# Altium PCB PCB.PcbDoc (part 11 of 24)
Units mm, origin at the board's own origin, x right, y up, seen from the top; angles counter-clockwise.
Board outline 100 x 160 mm, 10 copper layers (TOP_L1, L2, L3, L4, L5, L6, L7, L8, L9, BOTTOM_L10), stack 1.946 mm thick; 1358 components, 1149 nets, 6777 pads, 10914 vias.
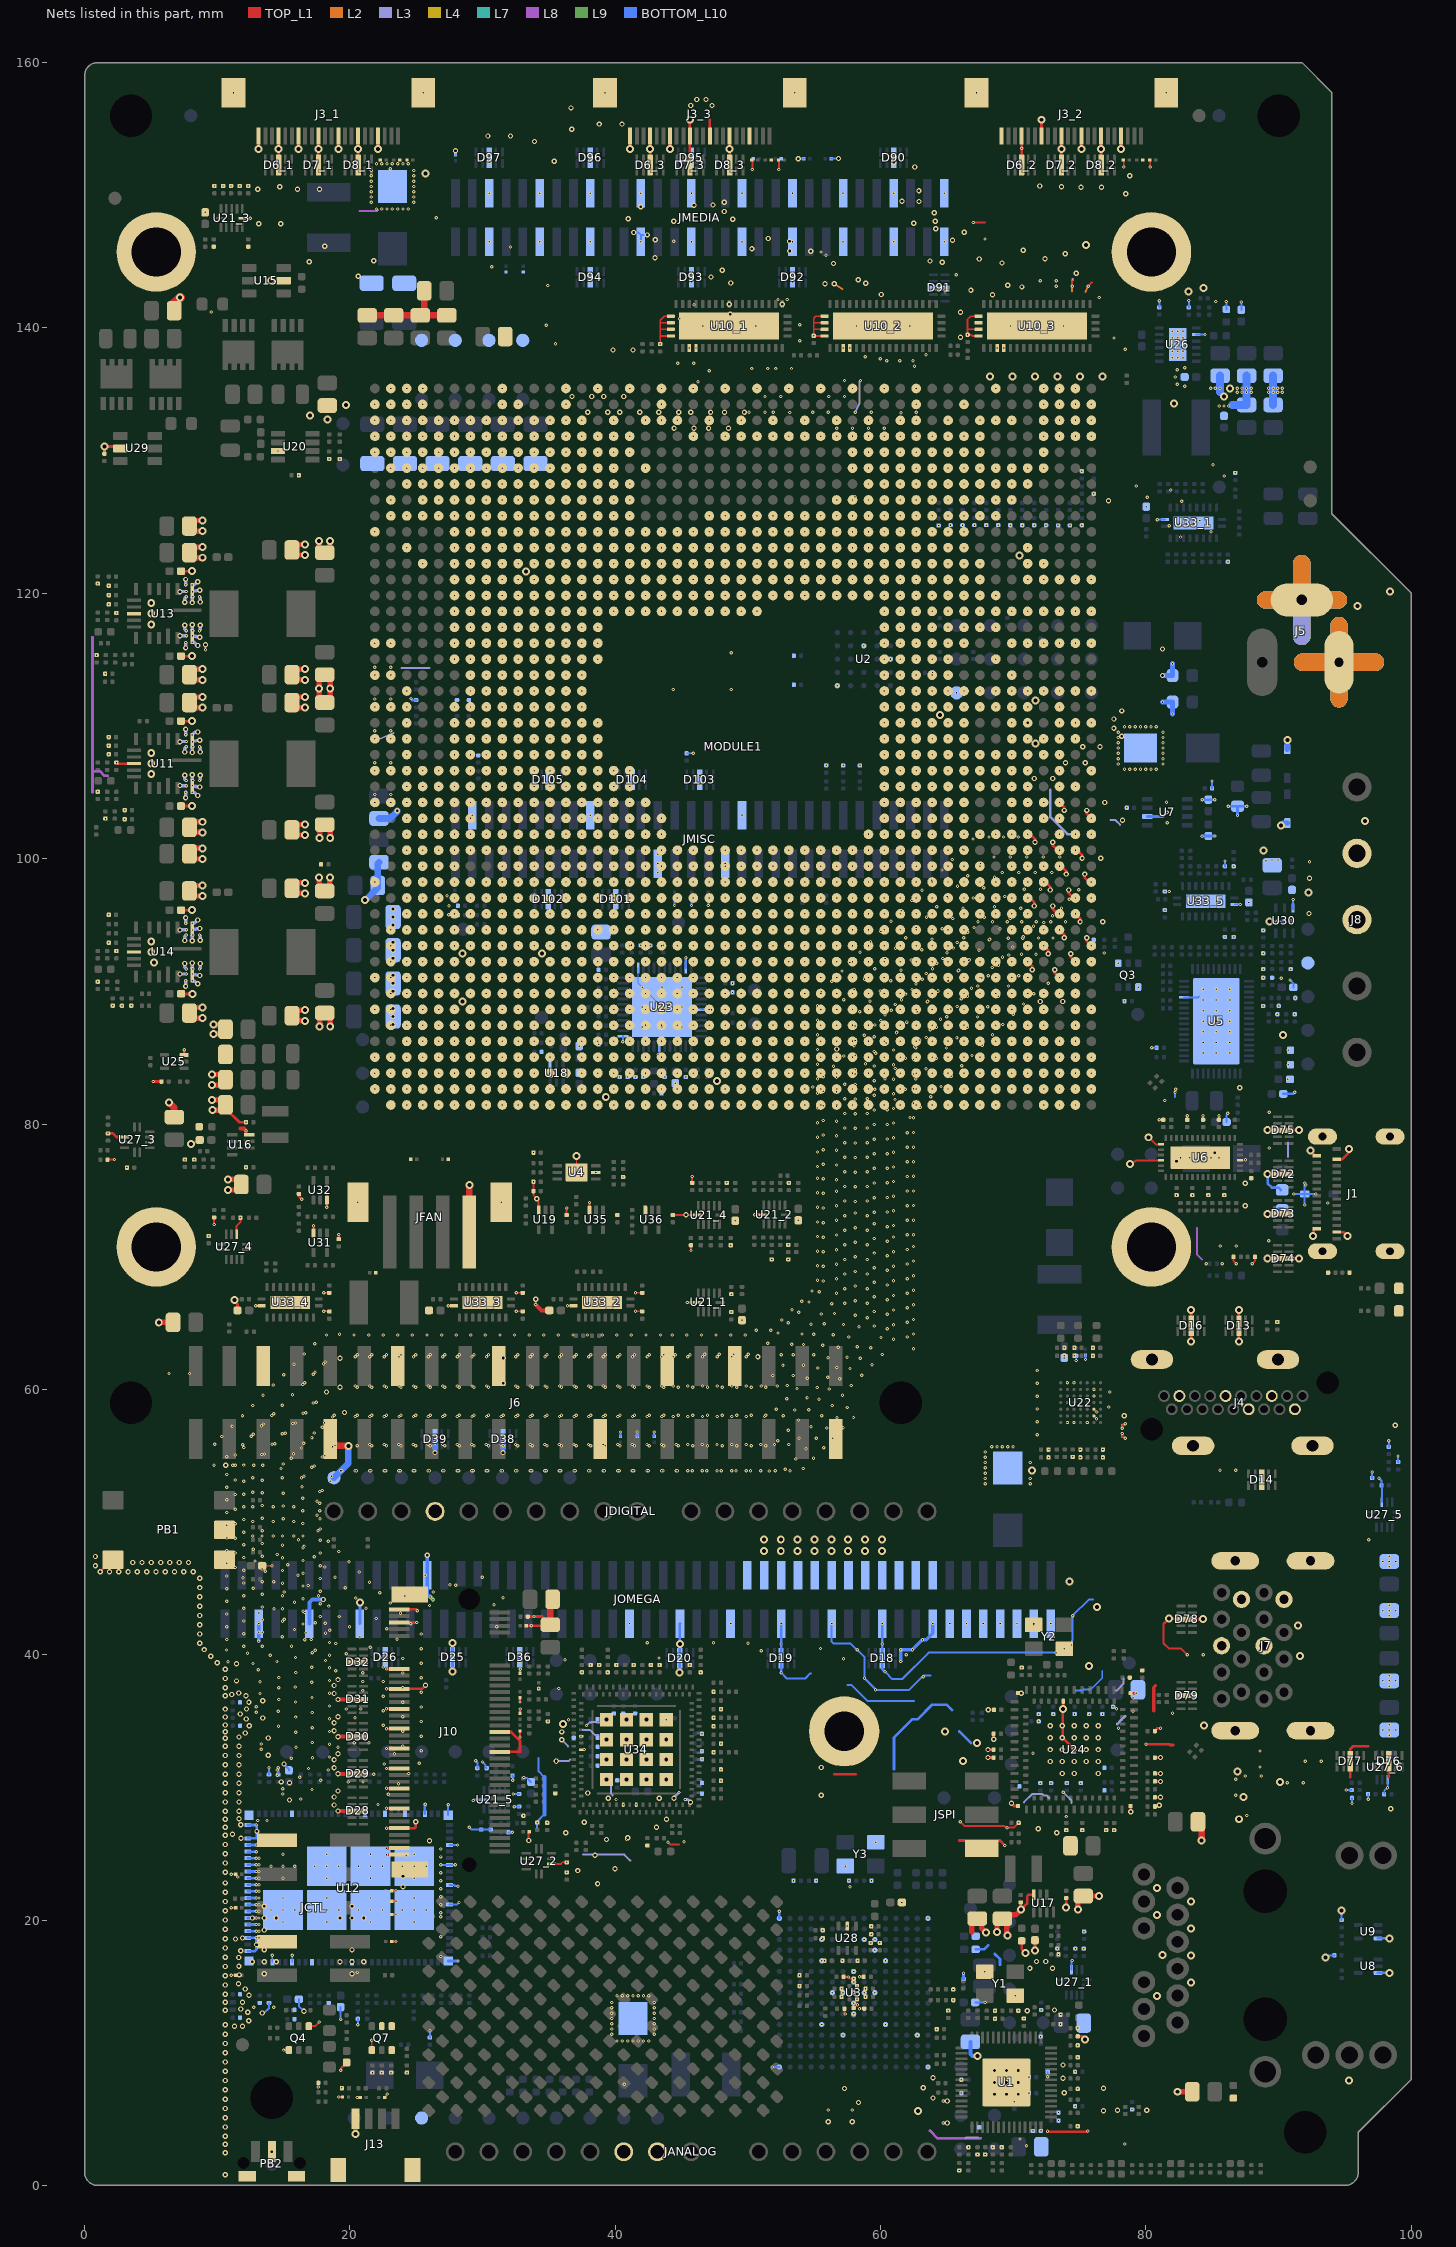
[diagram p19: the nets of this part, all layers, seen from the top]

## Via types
v1: diameter 0.25, hole 0.1, TOP_L1 to L2, tented both sides, 3439 vias
v2: diameter 0.25, hole 0.1, L2 to L3, tented both sides, 2256 vias
v3: diameter 0.25, hole 0.1, L9 to BOTTOM_L10, tented both sides, 1685 vias
v4: diameter 0.25, hole 0.1, L8 to L9, tented both sides, 1675 vias
v5: diameter 0.4, hole 0.2, L3 to L8, tented both sides, 1251 vias
v6: diameter 0.6, hole 0.3, TOP_L1 to BOTTOM_L10, tented both sides, 600 vias
v7: diameter 0.24, hole 0.1, TOP_L1 to L2, tented both sides, 8 vias

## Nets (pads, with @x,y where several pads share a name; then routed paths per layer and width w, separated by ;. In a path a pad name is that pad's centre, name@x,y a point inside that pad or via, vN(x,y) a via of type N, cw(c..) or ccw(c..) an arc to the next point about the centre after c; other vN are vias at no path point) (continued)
GND: C1.1 C2.1 C3.1 C4.1 C5.1 C6.1 C7.1 C8.1 C9.1 C10.1 C11.1 C12.1 C13.1 C14.1 C15.1 C16.1 C17.1 C18.1 C19.1 C20.1 C21.1 C22.1 C23.2 C24.2 C25.1 C26.1 C27.1 C28.1 C29.1 C30.1 C31.1 C32.1 C33.1 C34.1 C35.1 C36.1 C37.1 C38.1 C39.1 C40.1 C41.1 C42.1 C43.1 C44.2 C45.1 C46.1 C47.1 C48.1 C49.1 C54.1 C55.1 C56.1 C57.1 C58.1 C59.1 C60.1 C61.1 C62.1 C63.1 C64.2 C65.1 C66.2 C67.1 C68.1 C69_1.1 C69_2.1 C69_3.1 C70.2 C71.1 C72.1 C73.2 C74.2 C76.2 C77.2 C78.2 C79.2 C81.1 C82.1 C83.1 C84.1 C85.1 C87.2 C88.2 C89.2 C90.2 C92.2 C93.2 C94.1 C95.1 C97.2 C98.2 C99.2 C100.2 C101.1 C103.1 C104.1 C105.2 C106.1 C107.1 C108.1 C109.1 C110.1 C111.1 C114.1 C115.1 C116.2 C117.1 C118.1 C119.1 C120.1 C122.1 C123.1 C124.1 C125.1 C127.2 C128.1 C129.1 C130.1 C131.1 C132.2 C133.2 C134.1 C135.2 C136.1 C137.1 C139.2 C140.2 C141.2 C142.2 C143.2 C144.1 C145.1 C146.1 C147.1 C148.2 C149.2 C150.1 C151.1 C152.1 C153.1 C154.1 C155.1 C156.1 C157.1 C158.1 C159.1 C160.1 C161.1 C163.1 C164.1 C165.1 C166.1 C167.1 C168.1 C169.1 C170.1 C171.1 C172_1.1 C172_2.1 C172_3.1 C172_4.1 C172_5.1 C173_1.1 C173_2.1 C173_3.1 C173_4.1 C173_5.1 C174_1.1 C174_2.1 C174_3.1 C174_4.1 C174_5.1 C175_1.1 C175_2.1 C175_3.1 C175_4.1 C175_5.1 C176_1.2 C176_2.2 C176_3.2 C176_4.2 C176_5.2 C177.1 C178.1 C179_1.1 C179_2.1 C179_3.1 C179_4.1 C179_5.1 C179_6.1 C180.1 C181.1 C182.1 C183.1 C184.1 C185.1 C186.1 C187.1 C188.1 C189.1 C190.1 C191.1 C192.1 C193.1 C194.1 C195.1 C196.1 C197.1 C198.1 C199.1 C200.1 C201.1 C202.1 C203.1 C204.1 C205.1 C206.1 C207.1 C208.1 C210.1 C211.1 C212.1 C213.1 C214.1 C215.1 C216.1 C220_1.2 C220_2.2 C220_3.2 C220_4.2 C220_5.2 C221.1 C222.1 C223.1 C224.1 C225.1 C226.1 C227.1 C228.1 C229.1 C230.1 C231.1 C232.1 C233.1 C234.1 C235.1 C236.1 C237.1 C238.1 C239.1 C240.1 C241.1 C242.1 C243.1 C244.1 C245.1 C246_1.1 C246_2.1 C246_3.1 C246_4.1 C246_5.1 C246_6.1 C248.1 C249.1 C250.1 C251.1 C252.1 C255.1 C257.1 C258.1 C259.2 C260.1 C261.2 C262.1 C263.1 C264.2 C265.1 C266.1 C267.1 C268.1 C269.1 C270.1 C271.1 C272.1 C273.1 C274.1 C275.1 C276.1 C277.1 C278.1 C279.1 C281.1 C282.1 C285.1 C286.2 C287.2 C288.2 C291.1 C292.1 C294.1 C295.1 C296.2 C300.1 C302.1 C303.2 C304.1 C305.1 C306.1 C308.1 C311.1 C312.1 C313.1 C314.1 C315.1 C316.1 C317.1 C318.1 C319.2 C320.2 C321.2 C328.1 C329.1 C330.1 C331.1 C332.2 C333.2 C334.2 C335.2 C336.2 C337.2 C338.1 C339.2 C340.2 C341.2 C342.2 C343.2 C344.2 C345.1 C346.1 C347.1 C348.1 C351.2 C352.2 C353.2 C354.2 C355.1 C356.2 C357.2 C359.1 C360.1 C361.2 D1.1 D2.1 D5.1 D6_1.3 D6_1.8 D6_2.3 D6_2.8 D6_3.3 D6_3.8 D7_1.3 D7_1.8 D7_2.3 D7_2.8 D7_3.3 D7_3.8 D8_1.3 D8_1.8 D8_2.3 D8_2.8 D8_3.3 D8_3.8 D10_1.1 D10_2.1 D10_3.1 D11_1.1 D11_2.1 D11_3.1 D12.1 D13.3 D13.8 D14.3 D14.8 D15_1.1 D15_2.1 D15_3.1 D16.3 D16.8 D17.1 D18.3 D18.8 D19.3 D19.8 D20.3 D20.8 D21.1 D22.1 D23.1 D24.1 D25.3 D25.8 D26.3 D26.8 D27.1 D28.3 D28.8 D29.3 D29.8 D30.3 D30.8 D31.3 D31.8 D32.3 D32.8 D33.1 D34.1 D35.1 D36.3 D36.8 D37.1 D38.3 D38.8 D39.3 D39.8 D40.1 D41.1 D42.1 D43.1 D61.1 D62.1 D63.1 D64.1 D65.1 D66.1 D67.1 D69.1 D70.1 D71.1 D72.3 D72.8 D73.3 D73.8 D74.3 D74.8 D75.3 D75.8 D76.3 D76.8 D77.3 D77.8 D78.3 D78.8 D79.3 D79.8 D80.1 D81.1 D82.1 D83.1 D84.1 D85.1 D86.1 D87.1 D88.1 D89.1 D90.3 D90.8 D91.3 D91.8 D92.3 D92.8 D93.3 D93.8 D94.3 D94.8 D95.3 D95.8 D96.3 D96.8 D97.3 D97.8 D98.1 D99.1 D100.1 D101.3 D101.8 D102.3 D102.8 D103.3 D103.8 D104.3 D104.8 D105.3 D105.8 D106.1 DL2.C DL3.C H1.1 H2.1 H3.1 H4.1 H5.1 J1.A1 J1.A12 J1.B1 J1.B12 J1.SHIELD1 J1.SHIELD2 J1.SHIELD3 J1.SHIELD4 J3_1.1 J3_1.4 J3_1.7 J3_1.10 J3_1.13 J3_1.16 J3_1.19 J3_1.FIX J3_2.1 J3_2.4 J3_2.7 J3_2.10 J3_2.13 J3_2.16 J3_2.19 J3_2.FIX J3_3.1 J3_3.4 J3_3.7 J3_3.10 J3_3.13 J3_3.16 J3_3.19 J3_3.FIX J4.2 J4.5 J4.8 J4.11 J4.17 J4.SH1 J4.SH2 J4.SH3 J4.SH4 J5.2 J5.3 J6.6 J6.9 J6.14 J6.20 J6.25 J6.30 J6.34 J6.39 J7.4 J7.7 J7.13 J7.16 J7.19 J7.20 J7.21 J7.22 J8.2 J8.3 J10.1 J10.3 J10.9 J10.15 J10.21 J10.27 J10.32 J10.33 J10.38 J10.39 J10.45 J10.51 J10.57 J10.71 J10.75 J10.FIXING J13.1 J13.FIX JANALOG.6 JANALOG.7 JCTL.1 JCTL.7 JDIGITAL.15 JFAN.4 JFAN.FIX JMEDIA.1 JMEDIA.2 JMEDIA.7 JMEDIA.8 JMEDIA.13 JMEDIA.14 JMEDIA.19 JMEDIA.20 JMEDIA.25 JMEDIA.26 JMEDIA.31 JMEDIA.32 JMEDIA.37 JMEDIA.38 JMEDIA.43 JMEDIA.44 JMEDIA.49 JMEDIA.50 JMEDIA.55 JMEDIA.56 JMISC.26 JMISC.27 JMISC.35 JMISC.44 JMISC.58 JOMEGA.2 JOMEGA.4 JOMEGA.6 JOMEGA.8 JOMEGA.10 JOMEGA.12 JOMEGA.14 JOMEGA.15 JOMEGA.16 JOMEGA.17 JOMEGA.19 JOMEGA.21 JOMEGA.22 JOMEGA.23 JOMEGA.25 JOMEGA.27 JOMEGA.28 JOMEGA.29 JOMEGA.31 JOMEGA.33 JOMEGA.34 JOMEGA.35 JOMEGA.37 JOMEGA.40 JOMEGA.46 JOMEGA.52 JOMEGA.75 JOMEGA.84 JOMEGA.90 JOMEGA.96 JSPI.6 MODULE1.A2 MODULE1.A3 MODULE1.A4 MODULE1.A7 MODULE1.A9 MODULE1.A15 MODULE1.A20 MODULE1.A22 MODULE1.A24 MODULE1.A26 MODULE1.A28 MODULE1.A30 MODULE1.A37 MODULE1.A42 MODULE1.A43 MODULE1.A44 MODULE1.A45 MODULE1.AA1 MODULE1.AA2 MODULE1.AA3 MODULE1.AA4 MODULE1.AA5 MODULE1.AA6 MODULE1.AA7 MODULE1.AA8 MODULE1.AA9 MODULE1.AA10 MODULE1.AA11 MODULE1.AA12 MODULE1.AA13 MODULE1.AA14 MODULE1.AA15 MODULE1.AA16 MODULE1.AA17 MODULE1.AA32 MODULE1.AA33 MODULE1.AA34 MODULE1.AA35 MODULE1.AA36 MODULE1.AA37 MODULE1.AA43 MODULE1.AA46 MODULE1.AB1 MODULE1.AB2 MODULE1.AB3 MODULE1.AB4 MODULE1.AB5 MODULE1.AB6 MODULE1.AB7 MODULE1.AB8 MODULE1.AB9 MODULE1.AB10 MODULE1.AB11 MODULE1.AB12 MODULE1.AB13 MODULE1.AB14 MODULE1.AB15 MODULE1.AB16 MODULE1.AB17 MODULE1.AB32 MODULE1.AB33 MODULE1.AB34 MODULE1.AB35 MODULE1.AB36 MODULE1.AB37 MODULE1.AB38 MODULE1.AB44 MODULE1.AC1 MODULE1.AC2 MODULE1.AC3 MODULE1.AC4 MODULE1.AC5 MODULE1.AC6 MODULE1.AC7 MODULE1.AC8 MODULE1.AC9 MODULE1.AC10 MODULE1.AC11 MODULE1.AC12 MODULE1.AC13 MODULE1.AC14 MODULE1.AC15 MODULE1.AC16 MODULE1.AC17 MODULE1.AC32 MODULE1.AC33 MODULE1.AC34 MODULE1.AC35 MODULE1.AC36 MODULE1.AC37 MODULE1.AC38 MODULE1.AC43 MODULE1.AC46 MODULE1.AD1 MODULE1.AD2 MODULE1.AD3 MODULE1.AD4 MODULE1.AD5 MODULE1.AD6 MODULE1.AD7 MODULE1.AD8 MODULE1.AD9 MODULE1.AD10 MODULE1.AD11 MODULE1.AD12 MODULE1.AD13 MODULE1.AD14 MODULE1.AD15 MODULE1.AD16 MODULE1.AD17 MODULE1.AD32 MODULE1.AD33 MODULE1.AD34 MODULE1.AD35 MODULE1.AD36 MODULE1.AD37 MODULE1.AD38 MODULE1.AD43 MODULE1.AD44 MODULE1.AE1 MODULE1.AE2 MODULE1.AE3 MODULE1.AE4 MODULE1.AE5 MODULE1.AE6 MODULE1.AE7 MODULE1.AE8 MODULE1.AE9 MODULE1.AE10 MODULE1.AE11 MODULE1.AE12 MODULE1.AE13 MODULE1.AE14 MODULE1.AE15 MODULE1.AE16 MODULE1.AE17 MODULE1.AE32 MODULE1.AE33 MODULE1.AE34 MODULE1.AE35 MODULE1.AE36 MODULE1.AE37 MODULE1.AE38 MODULE1.AE43 MODULE1.AE46 MODULE1.AF1 MODULE1.AF2 MODULE1.AF3 MODULE1.AF4 MODULE1.AF5 MODULE1.AF6 MODULE1.AF7 MODULE1.AF8 MODULE1.AF9 MODULE1.AF10 MODULE1.AF11 MODULE1.AF12 MODULE1.AF13 MODULE1.AF14 MODULE1.AF15 MODULE1.AF16 MODULE1.AF17 MODULE1.AF33 MODULE1.AF34 MODULE1.AF35 MODULE1.AF36 MODULE1.AF37 MODULE1.AF38 MODULE1.AF43 MODULE1.AF44 MODULE1.AG1 MODULE1.AG2 MODULE1.AG3 MODULE1.AG4 MODULE1.AG5 MODULE1.AG6 MODULE1.AG7 MODULE1.AG8 MODULE1.AG9 MODULE1.AG10 MODULE1.AG11 MODULE1.AG12 MODULE1.AG13 MODULE1.AG14 MODULE1.AG15 MODULE1.AG16 MODULE1.AG17 MODULE1.AG33 MODULE1.AG34 MODULE1.AG35 MODULE1.AG36 MODULE1.AG37 MODULE1.AG38 MODULE1.AG43 MODULE1.AG46 MODULE1.AH1 MODULE1.AH2 MODULE1.AH3 MODULE1.AH4 MODULE1.AH5 MODULE1.AH6 MODULE1.AH7 MODULE1.AH8 MODULE1.AH9 MODULE1.AH10 MODULE1.AH11 MODULE1.AH12 MODULE1.AH13 MODULE1.AH14 MODULE1.AH15 MODULE1.AH16 MODULE1.AH17 MODULE1.AH33 MODULE1.AH34 MODULE1.AH35 MODULE1.AH36 MODULE1.AH37 MODULE1.AH38 MODULE1.AH43 MODULE1.AH44 MODULE1.AJ1 MODULE1.AJ2 MODULE1.AJ3 MODULE1.AJ4 MODULE1.AJ5 MODULE1.AJ6 MODULE1.AJ7 MODULE1.AJ8 MODULE1.AJ9 MODULE1.AJ10 MODULE1.AJ11 MODULE1.AJ12 MODULE1.AJ13 MODULE1.AJ14 MODULE1.AJ15 MODULE1.AJ16 MODULE1.AJ17 MODULE1.AJ33 MODULE1.AJ34 MODULE1.AJ35 MODULE1.AJ36 MODULE1.AJ37 MODULE1.AJ38 MODULE1.AJ43 MODULE1.AJ46 MODULE1.AK1 MODULE1.AK2 MODULE1.AK3 MODULE1.AK4 MODULE1.AK5 MODULE1.AK6 MODULE1.AK7 MODULE1.AK8 MODULE1.AK9 MODULE1.AK10 MODULE1.AK11 MODULE1.AK12 MODULE1.AK13 MODULE1.AK14 MODULE1.AK15 MODULE1.AK16 MODULE1.AK17 MODULE1.AK33 MODULE1.AK34 MODULE1.AK35 MODULE1.AK36 MODULE1.AK37 MODULE1.AK38 MODULE1.AK39 MODULE1.AK43 MODULE1.AK44 MODULE1.AL1 MODULE1.AL2 MODULE1.AL3 MODULE1.AL4 MODULE1.AL5 MODULE1.AL6 MODULE1.AL7 MODULE1.AL8 MODULE1.AL9 MODULE1.AL10 MODULE1.AL11 MODULE1.AL12 MODULE1.AL13 MODULE1.AL14 MODULE1.AL15 MODULE1.AL16 MODULE1.AL17 MODULE1.AL33 MODULE1.AL34 MODULE1.AL35 MODULE1.AL36 MODULE1.AL37 MODULE1.AL38 MODULE1.AL39 MODULE1.AL41 MODULE1.AL42 MODULE1.AL43 MODULE1.AL46 MODULE1.AM1 MODULE1.AM2 MODULE1.AM3 MODULE1.AM4 MODULE1.AM5 MODULE1.AM6 MODULE1.AM7 MODULE1.AM8 MODULE1.AM9 MODULE1.AM10 MODULE1.AM11 MODULE1.AM12 MODULE1.AM13 MODULE1.AM14 MODULE1.AM15 MODULE1.AM16 MODULE1.AM17 MODULE1.AM18 MODULE1.AM33 MODULE1.AM34 MODULE1.AM35 MODULE1.AM36 MODULE1.AM37 MODULE1.AM38 MODULE1.AM39 MODULE1.AM40 MODULE1.AM41 MODULE1.AM42 MODULE1.AM43 MODULE1.AM44 MODULE1.AN1 MODULE1.AN2 MODULE1.AN3 MODULE1.AN4 MODULE1.AN5 MODULE1.AN6 MODULE1.AN7 MODULE1.AN8 MODULE1.AN9 MODULE1.AN10 MODULE1.AN11 MODULE1.AN12 MODULE1.AN13 MODULE1.AN14 MODULE1.AN15 MODULE1.AN16 MODULE1.AN17 MODULE1.AN18 MODULE1.AN19 MODULE1.AN20 MODULE1.AN21 MODULE1.AN22 MODULE1.AN23 MODULE1.AN24 MODULE1.AN25 MODULE1.AN26 MODULE1.AN27 MODULE1.AN28 MODULE1.AN29 MODULE1.AN30 MODULE1.AN31 MODULE1.AN32 MODULE1.AN33 MODULE1.AN34 MODULE1.AN35 MODULE1.AN36 MODULE1.AN37 MODULE1.AN38 MODULE1.AN39 MODULE1.AN40 MODULE1.AN41 MODULE1.AN42 MODULE1.AN43 MODULE1.AN46 MODULE1.AP1 MODULE1.AP2 MODULE1.AP3 MODULE1.AP4 MODULE1.AP5 MODULE1.AP6 MODULE1.AP7 MODULE1.AP8 MODULE1.AP9 MODULE1.AP10 MODULE1.AP11 MODULE1.AP12 MODULE1.AP13 MODULE1.AP14 MODULE1.AP15 MODULE1.AP16 MODULE1.AP17 MODULE1.AP18 MODULE1.AP19 MODULE1.AP20 MODULE1.AP21 MODULE1.AP22 MODULE1.AP23 MODULE1.AP24 MODULE1.AP25 MODULE1.AP26 MODULE1.AP27 MODULE1.AP28 MODULE1.AP29 MODULE1.AP30 MODULE1.AP31 MODULE1.AP32 MODULE1.AP33 MODULE1.AP34 MODULE1.AP35 MODULE1.AP36 MODULE1.AP37 MODULE1.AP38 MODULE1.AP39 MODULE1.AP40 MODULE1.AP41 MODULE1.AP42 MODULE1.AP43 MODULE1.AP44 MODULE1.AR1 MODULE1.AR2 MODULE1.AR3 MODULE1.AR4 MODULE1.AR5 MODULE1.AR6 MODULE1.AR7 MODULE1.AR8 MODULE1.AR9 MODULE1.AR10 MODULE1.AR11 MODULE1.AR12 MODULE1.AR13 MODULE1.AR14 MODULE1.AR15 MODULE1.AR16 MODULE1.AR17 MODULE1.AR18 MODULE1.AR19 MODULE1.AR20 MODULE1.AR21 MODULE1.AR22 MODULE1.AR23 MODULE1.AR24 MODULE1.AR25 MODULE1.AR26 MODULE1.AR27 MODULE1.AR28 MODULE1.AR29 MODULE1.AR30 MODULE1.AR31 MODULE1.AR32 MODULE1.AR33 MODULE1.AR34 MODULE1.AR35 MODULE1.AR36 MODULE1.AR37 MODULE1.AR38 MODULE1.AR39 MODULE1.AR40 MODULE1.AR41 MODULE1.AR42 MODULE1.AR43 MODULE1.AR44 MODULE1.AR45 MODULE1.AR46 MODULE1.AT1 MODULE1.AT2 MODULE1.AT3 MODULE1.AT4 MODULE1.AT5 MODULE1.AT6 MODULE1.AT7 MODULE1.AT8 MODULE1.AT9 MODULE1.AT10 MODULE1.AT11 MODULE1.AT12 MODULE1.AT13 MODULE1.AT14 MODULE1.AT15 MODULE1.AT16 MODULE1.AT17 MODULE1.AT18 MODULE1.AT19 MODULE1.AT20 MODULE1.AT21 MODULE1.AT22 MODULE1.AT23 MODULE1.AT24 MODULE1.AT25 MODULE1.AT26 MODULE1.AT27 MODULE1.AT28 MODULE1.AT29 MODULE1.AT30 MODULE1.AT31 MODULE1.AT32 MODULE1.AT33 MODULE1.AT34 MODULE1.AT35 MODULE1.AT36 MODULE1.AT37 MODULE1.AT38 MODULE1.AT39 MODULE1.AT40 MODULE1.AT41 MODULE1.AT42 MODULE1.AT43 MODULE1.AU1 MODULE1.AU2 MODULE1.AU3 MODULE1.AU4 MODULE1.AU5 MODULE1.AU6 MODULE1.AU7 MODULE1.AU8 MODULE1.AU9 MODULE1.AU10 MODULE1.AU11 MODULE1.AU12 MODULE1.AU13 MODULE1.AU14 MODULE1.AU15 MODULE1.AU16 MODULE1.AU17 MODULE1.AU18 MODULE1.AU19 MODULE1.AU20 MODULE1.AU21 MODULE1.AU22 MODULE1.AU23 MODULE1.AU24 MODULE1.AU25 MODULE1.AU26 MODULE1.AU27 MODULE1.AU28 MODULE1.AU29 MODULE1.AU30 MODULE1.AU31 MODULE1.AU32 MODULE1.AU33 MODULE1.AU34 MODULE1.AU35 MODULE1.AU36 MODULE1.AU37 MODULE1.AU38 MODULE1.AU39 MODULE1.AU40 MODULE1.AU41 MODULE1.AU42 MODULE1.AU43 MODULE1.AU44 MODULE1.AV1 MODULE1.AV2 MODULE1.AV3 MODULE1.AV4 MODULE1.AV5 MODULE1.AV6 MODULE1.AV7 MODULE1.AV8 MODULE1.AV9 MODULE1.AV10 MODULE1.AV11 MODULE1.AV12 MODULE1.AV13 MODULE1.AV14 MODULE1.AV15 MODULE1.AV16 MODULE1.AV17 MODULE1.AV18 MODULE1.AV19 MODULE1.AV20 MODULE1.AV21 MODULE1.AV22 MODULE1.AV23 MODULE1.AV24 MODULE1.AV25 MODULE1.AV26 MODULE1.AV27 MODULE1.AV30 MODULE1.AV31 MODULE1.AV32 MODULE1.AV33 MODULE1.AV34 MODULE1.AV35 MODULE1.AV36 MODULE1.AV37 MODULE1.AV38 MODULE1.AV39 MODULE1.AV40 MODULE1.AV41 MODULE1.AV42 MODULE1.AV43 MODULE1.AV45 MODULE1.AW1 MODULE1.AW2 MODULE1.AW3 MODULE1.AW4 MODULE1.AW5 MODULE1.AW6 MODULE1.AW7 MODULE1.AW8 MODULE1.AW9 MODULE1.AW10 MODULE1.AW13 MODULE1.AW14 MODULE1.AW15 MODULE1.AW16 MODULE1.AW18 MODULE1.AW21 MODULE1.AW22 MODULE1.AW23 MODULE1.AW26 MODULE1.AW27 MODULE1.AW31 MODULE1.AW32 MODULE1.AW33 MODULE1.AW34 MODULE1.AW35 MODULE1.AW38 MODULE1.AW39 MODULE1.AW40 MODULE1.AW41 MODULE1.AW42 MODULE1.AW43 MODULE1.AW44 MODULE1.AY1 MODULE1.AY2 MODULE1.AY3 MODULE1.AY4 MODULE1.AY5 MODULE1.AY6 MODULE1.AY7 MODULE1.AY8 MODULE1.AY9 MODULE1.AY10 MODULE1.AY13 MODULE1.AY14 MODULE1.AY15 MODULE1.AY18 MODULE1.AY21 MODULE1.AY22 MODULE1.AY23 MODULE1.AY26 MODULE1.AY27 MODULE1.AY29 MODULE1.AY31 MODULE1.AY32 MODULE1.AY33 MODULE1.AY38 MODULE1.AY39 MODULE1.AY40 MODULE1.AY41 MODULE1.AY44 MODULE1.AY46 MODULE1.B1 MODULE1.B2 MODULE1.B3 MODULE1.B4 MODULE1.B6 MODULE1.B7 MODULE1.B8 MODULE1.B9 MODULE1.B10 MODULE1.B11 MODULE1.B12 MODULE1.B20 MODULE1.B22 MODULE1.B24 MODULE1.B26 MODULE1.B28 MODULE1.B30 MODULE1.B38 MODULE1.B39 MODULE1.B41 MODULE1.B42 MODULE1.B43 MODULE1.B44 MODULE1.B45 MODULE1.B46 MODULE1.BA2 MODULE1.BA3 MODULE1.BA4 MODULE1.BA5 MODULE1.BA6 MODULE1.BA7 MODULE1.BA8 MODULE1.BA9 MODULE1.BA10 MODULE1.BA12 MODULE1.BA13 MODULE1.BA14 MODULE1.BA15 MODULE1.BA16 MODULE1.BA17 MODULE1.BA18 MODULE1.BA19 MODULE1.BA20 MODULE1.BA21 MODULE1.BA22 MODULE1.BA23 MODULE1.BA24 MODULE1.BA25 MODULE1.BA26 MODULE1.BA27 MODULE1.BA28 MODULE1.BA30 MODULE1.BA32 MODULE1.BA39 MODULE1.BA40 MODULE1.BA41 MODULE1.BA44 MODULE1.BB2 MODULE1.BB3 MODULE1.BB4 MODULE1.BB5 MODULE1.BB6 MODULE1.BB7 MODULE1.BB8 MODULE1.BB9 MODULE1.BB10 MODULE1.BB11 MODULE1.BB12 MODULE1.BB13 MODULE1.BB14 MODULE1.BB15 MODULE1.BB16 MODULE1.BB17 MODULE1.BB18 MODULE1.BB19 MODULE1.BB20 MODULE1.BB21 MODULE1.BB22 MODULE1.BB23 MODULE1.BB24 MODULE1.BB25 MODULE1.BB26 MODULE1.BB27 MODULE1.BB30 MODULE1.BB32 MODULE1.BB34 MODULE1.BB35 MODULE1.BB36 MODULE1.BB40 MODULE1.BB41 MODULE1.BC1 MODULE1.BC2 MODULE1.BC3 MODULE1.BC4 MODULE1.BC5 MODULE1.BC6 MODULE1.BC7 MODULE1.BC8 MODULE1.BC11 MODULE1.BC12 MODULE1.BC15 MODULE1.BC16 MODULE1.BC19 MODULE1.BC20 MODULE1.BC23 MODULE1.BC24 MODULE1.BC27 MODULE1.BC30 MODULE1.BC32 MODULE1.BC34 MODULE1.BC35 MODULE1.BC41 MODULE1.BC42 MODULE1.BC43 MODULE1.BC44 MODULE1.BC45 MODULE1.BC46 MODULE1.BD1 MODULE1.BD2 MODULE1.BD3 MODULE1.BD4 MODULE1.BD5 MODULE1.BD8 MODULE1.BD9 MODULE1.BD12 MODULE1.BD13 MODULE1.BD16 MODULE1.BD17 MODULE1.BD18 MODULE1.BD19 MODULE1.BD20 MODULE1.BD21 MODULE1.BD22 MODULE1.BD23 MODULE1.BD24 MODULE1.BD25 MODULE1.BD26 MODULE1.BD27 MODULE1.BD30 MODULE1.BD32 MODULE1.BD34 MODULE1.BD43 MODULE1.BD44 MODULE1.BD45 MODULE1.BD46 MODULE1.BE1 MODULE1.BE2 MODULE1.BE3 MODULE1.BE4 MODULE1.BE5 MODULE1.BE6 MODULE1.BE7 MODULE1.BE8 MODULE1.BE9 MODULE1.BE10 MODULE1.BE13 MODULE1.BE14 MODULE1.BE17 MODULE1.BE18 MODULE1.BE21 MODULE1.BE24 MODULE1.BE25 MODULE1.BE27 MODULE1.BE30 MODULE1.BE32 MODULE1.BE34 MODULE1.BE43 MODULE1.BE44 MODULE1.BE45 MODULE1.BE46 MODULE1.BF2 MODULE1.BF3 MODULE1.BF4 MODULE1.BF7 MODULE1.BF10 MODULE1.BF11 MODULE1.BF14 MODULE1.BF15 MODULE1.BF18 MODULE1.BF19 MODULE1.BF22 MODULE1.BF25 MODULE1.BF27 MODULE1.BF30 MODULE1.BF32 MODULE1.BF34 MODULE1.BF43 MODULE1.BF44 MODULE1.BF45 MODULE1.C1 MODULE1.C2 MODULE1.C3 MODULE1.C4 MODULE1.C5 MODULE1.C6 MODULE1.C7 MODULE1.C8 MODULE1.C9 MODULE1.C10 MODULE1.C11 MODULE1.C12 MODULE1.C13 MODULE1.C14 MODULE1.C15 MODULE1.C16 MODULE1.C17 MODULE1.C18 MODULE1.C19 MODULE1.C20 MODULE1.C21 MODULE1.C22 MODULE1.C23 MODULE1.C24 MODULE1.C25 MODULE1.C26 MODULE1.C27 MODULE1.C36 MODULE1.C38 MODULE1.C40 MODULE1.C41 MODULE1.C42 MODULE1.C43 MODULE1.C44 MODULE1.C45 MODULE1.C46 MODULE1.D1 MODULE1.D2 MODULE1.D3 MODULE1.D4 MODULE1.D5 MODULE1.D6 MODULE1.D7 MODULE1.D8 MODULE1.D9 MODULE1.D10 MODULE1.D11 MODULE1.D12 MODULE1.D13 MODULE1.D14 MODULE1.D15 MODULE1.D16 MODULE1.D17 MODULE1.D18 MODULE1.D19 MODULE1.D20 MODULE1.D21 MODULE1.D22 MODULE1.D35 MODULE1.D38 MODULE1.D39 MODULE1.D40 MODULE1.D41 MODULE1.D42 MODULE1.D43 MODULE1.D44 MODULE1.D45 MODULE1.D46 MODULE1.E1 MODULE1.E2 MODULE1.E3 MODULE1.E4 MODULE1.E5 MODULE1.E6 MODULE1.E7 MODULE1.E8 MODULE1.E9 MODULE1.E10 MODULE1.E11 MODULE1.E12 MODULE1.E13 MODULE1.E14 MODULE1.E15 MODULE1.E16 MODULE1.E17 MODULE1.E18 MODULE1.E19 MODULE1.E20 MODULE1.E21 MODULE1.E22 MODULE1.E38 MODULE1.E39 MODULE1.E40 MODULE1.E41 MODULE1.E42 MODULE1.E43 MODULE1.E44 MODULE1.F1 MODULE1.F2 MODULE1.F3 MODULE1.F4 MODULE1.F5 MODULE1.F6 MODULE1.F7 MODULE1.F8 MODULE1.F9 MODULE1.F10 MODULE1.F11 MODULE1.F12 MODULE1.F13 MODULE1.F14 MODULE1.F15 MODULE1.F16 MODULE1.F17 MODULE1.F18 MODULE1.F19 MODULE1.F20 MODULE1.F21 MODULE1.F22 MODULE1.F23 MODULE1.F24 MODULE1.F25 MODULE1.F26 MODULE1.F29 MODULE1.F30 MODULE1.F31 MODULE1.F32 MODULE1.F33 MODULE1.F34 MODULE1.F35 MODULE1.F36 MODULE1.F37 MODULE1.F38 MODULE1.F39 MODULE1.F40 MODULE1.F41 MODULE1.F42 MODULE1.F43 MODULE1.F44 MODULE1.G1 MODULE1.G2 MODULE1.G3 MODULE1.G4 MODULE1.G5 MODULE1.G6 MODULE1.G7 MODULE1.G8 MODULE1.G9 MODULE1.G10 MODULE1.G11 MODULE1.G12 MODULE1.G13 MODULE1.G14 MODULE1.G15 MODULE1.G17 MODULE1.G18 MODULE1.G19 MODULE1.G20 MODULE1.G21 MODULE1.G22 MODULE1.G23 MODULE1.G24 MODULE1.G25 MODULE1.G26 MODULE1.G27 MODULE1.G28 MODULE1.G29 MODULE1.G30 MODULE1.G31 MODULE1.G32 MODULE1.G33 MODULE1.G34 MODULE1.G35 MODULE1.G36 MODULE1.G37 MODULE1.G38 MODULE1.G39 MODULE1.G40 MODULE1.G41 MODULE1.G42 MODULE1.G43 MODULE1.G44 MODULE1.H1 MODULE1.H2 MODULE1.H3 MODULE1.H4 MODULE1.H5 MODULE1.H6 MODULE1.H7 MODULE1.H8 MODULE1.H9 MODULE1.H10 MODULE1.H11 MODULE1.H12 MODULE1.H13 MODULE1.H14 MODULE1.H15 MODULE1.H17 MODULE1.H18 MODULE1.H19 MODULE1.H20 MODULE1.H21 MODULE1.H22 MODULE1.H23 MODULE1.H24 MODULE1.H25 MODULE1.H26 MODULE1.H27 MODULE1.H28 MODULE1.H29 MODULE1.H30 MODULE1.H31 MODULE1.H32 MODULE1.H33 MODULE1.H34 MODULE1.H35 MODULE1.H36 MODULE1.H37 MODULE1.H38 MODULE1.H39 MODULE1.H40 MODULE1.H41 MODULE1.H42 MODULE1.H43 MODULE1.H44 MODULE1.J1 MODULE1.J2 MODULE1.J3 MODULE1.J4 MODULE1.J5 MODULE1.J6 MODULE1.J7 MODULE1.J8 MODULE1.J9 MODULE1.J10 MODULE1.J11 MODULE1.J12 MODULE1.J13 MODULE1.J14 MODULE1.J15 MODULE1.J16 MODULE1.J17 MODULE1.J18 MODULE1.J19 MODULE1.J20 MODULE1.J21 MODULE1.J22 MODULE1.J23 MODULE1.J24 MODULE1.J25 MODULE1.J26 MODULE1.J27 MODULE1.J28 MODULE1.J29 MODULE1.J30 MODULE1.J31 MODULE1.J32 MODULE1.J33 MODULE1.J34 MODULE1.J35 MODULE1.J36 MODULE1.J37 MODULE1.J38 MODULE1.J39 MODULE1.J40 MODULE1.J41 MODULE1.J42 MODULE1.J43 MODULE1.J44 MODULE1.J45 MODULE1.J46 MODULE1.K1 MODULE1.K2 MODULE1.K3 MODULE1.K4 MODULE1.K5 MODULE1.K6 MODULE1.K7 MODULE1.K8 MODULE1.K9 MODULE1.K10 MODULE1.K11 MODULE1.K12 MODULE1.K13 MODULE1.K14 MODULE1.K15 MODULE1.K16 MODULE1.K17 MODULE1.K18 MODULE1.K19 MODULE1.K20 MODULE1.K21 MODULE1.K22 MODULE1.K23 MODULE1.K24 MODULE1.K25 MODULE1.K26 MODULE1.K27 MODULE1.K28 MODULE1.K29 MODULE1.K30 MODULE1.K31 MODULE1.K32 MODULE1.K33 MODULE1.K34 MODULE1.K35 MODULE1.K36 MODULE1.K37 MODULE1.K38 MODULE1.K39 MODULE1.K40 MODULE1.K41 MODULE1.K42 MODULE1.K43 MODULE1.K44 MODULE1.K45 MODULE1.L1 MODULE1.L2 MODULE1.L3 MODULE1.L4 MODULE1.L5 MODULE1.L6 MODULE1.L7 MODULE1.L8 MODULE1.L9 MODULE1.L10 MODULE1.L11 MODULE1.L12 MODULE1.L13 MODULE1.L14 MODULE1.L15 MODULE1.L16 MODULE1.L17 MODULE1.L18 MODULE1.L19 MODULE1.L20 MODULE1.L21 MODULE1.L22 MODULE1.L23 MODULE1.L24 MODULE1.L25 MODULE1.L26 MODULE1.L27 MODULE1.L28 MODULE1.L29 MODULE1.L30 MODULE1.L31 MODULE1.L32 MODULE1.L33 MODULE1.L34 MODULE1.L35 MODULE1.L36 MODULE1.L37 MODULE1.L38 MODULE1.L39 MODULE1.L40 MODULE1.L41 MODULE1.L42 MODULE1.L43 MODULE1.L44 MODULE1.M1 MODULE1.M2 MODULE1.M3 MODULE1.M4 MODULE1.M5 MODULE1.M6 MODULE1.M7 MODULE1.M8 MODULE1.M9 MODULE1.M10 MODULE1.M11 MODULE1.M12 MODULE1.M13 MODULE1.M14 MODULE1.M15 MODULE1.M16 MODULE1.M17 MODULE1.M18 MODULE1.M19 MODULE1.M20 MODULE1.M21 MODULE1.M22 MODULE1.M23 MODULE1.M24 MODULE1.M25 MODULE1.M26 MODULE1.M27 MODULE1.M28 MODULE1.M29 MODULE1.M30 MODULE1.M31 MODULE1.M32 MODULE1.M33 MODULE1.M34 MODULE1.M35 MODULE1.M36 MODULE1.M37 MODULE1.M38 MODULE1.M39 MODULE1.M40 MODULE1.M41 MODULE1.M42 MODULE1.M43 MODULE1.M44 MODULE1.N1 MODULE1.N2 MODULE1.N3 MODULE1.N4 MODULE1.N5 MODULE1.N6 MODULE1.N7 MODULE1.N8 MODULE1.N9 MODULE1.N10 MODULE1.N11 MODULE1.N12 MODULE1.N13 MODULE1.N14 MODULE1.N15 MODULE1.N16 MODULE1.N17 MODULE1.N18 MODULE1.N19 MODULE1.N20 MODULE1.N21 MODULE1.N22 MODULE1.N23 MODULE1.N24 MODULE1.N25 MODULE1.N26 MODULE1.N27 MODULE1.N28 MODULE1.N29 MODULE1.N30 MODULE1.N31 MODULE1.N32 MODULE1.N33 MODULE1.N34 MODULE1.N35 MODULE1.N36 MODULE1.N37 MODULE1.N38 MODULE1.N39 MODULE1.N40 MODULE1.N41 MODULE1.N42 MODULE1.N43 MODULE1.N44 MODULE1.N45 MODULE1.N46 MODULE1.P1 MODULE1.P2 MODULE1.P3 MODULE1.P4 MODULE1.P5 MODULE1.P6 MODULE1.P7 MODULE1.P8 MODULE1.P9 MODULE1.P10 MODULE1.P11 MODULE1.P12 MODULE1.P13 MODULE1.P14 MODULE1.P15 MODULE1.P16 MODULE1.P17 MODULE1.P18 MODULE1.P19 MODULE1.P20 MODULE1.P21 MODULE1.P22 MODULE1.P23 MODULE1.P24 MODULE1.P25 MODULE1.P26 MODULE1.P27 MODULE1.P28 MODULE1.P29 MODULE1.P30 MODULE1.P31 MODULE1.P32 MODULE1.P33 MODULE1.P34 MODULE1.P35 MODULE1.P36 MODULE1.P37 MODULE1.P38 MODULE1.P39 MODULE1.P40 MODULE1.P41 MODULE1.P42 MODULE1.P43 MODULE1.P44 MODULE1.R1 MODULE1.R2 MODULE1.R3 MODULE1.R4 MODULE1.R5 MODULE1.R6 MODULE1.R7 MODULE1.R8 MODULE1.R9 MODULE1.R10 MODULE1.R11 MODULE1.R12 MODULE1.R13 MODULE1.R14 MODULE1.R15 MODULE1.R16 MODULE1.R17 MODULE1.R18 MODULE1.R19 MODULE1.R20 MODULE1.R21 MODULE1.R22 MODULE1.R23 MODULE1.R24 MODULE1.R25 MODULE1.R29 MODULE1.R30 MODULE1.R31 MODULE1.R32 MODULE1.R33 MODULE1.R34 MODULE1.R35 MODULE1.R36 MODULE1.R37 MODULE1.R38 MODULE1.R39 MODULE1.R40 MODULE1.R41 MODULE1.R42 MODULE1.R43 MODULE1.R46 MODULE1.T1 MODULE1.T2 MODULE1.T3 MODULE1.T4 MODULE1.T5 MODULE1.T6 MODULE1.T7 MODULE1.T8 MODULE1.T9 MODULE1.T10 MODULE1.T11 MODULE1.T12 MODULE1.T13 MODULE1.T14 MODULE1.T15 MODULE1.T16 MODULE1.T17 MODULE1.T18 MODULE1.T19 MODULE1.T20 MODULE1.T21 MODULE1.T22 MODULE1.T32 MODULE1.T33 MODULE1.T34 MODULE1.T35 MODULE1.T36 MODULE1.T37 MODULE1.T38 MODULE1.T39 MODULE1.T40 MODULE1.T41 MODULE1.T42 MODULE1.T43 MODULE1.T44 MODULE1.U1 MODULE1.U2 MODULE1.U3 MODULE1.U4 MODULE1.U5 MODULE1.U6 MODULE1.U7 MODULE1.U8 MODULE1.U9 MODULE1.U10 MODULE1.U11 MODULE1.U12 MODULE1.U13 MODULE1.U14 MODULE1.U15 MODULE1.U16 MODULE1.U17 MODULE1.U18 MODULE1.U19 MODULE1.U20 MODULE1.U21 MODULE1.U22 MODULE1.U32 MODULE1.U33 MODULE1.U34 MODULE1.U35 MODULE1.U36 MODULE1.U37 MODULE1.U38 MODULE1.U39 MODULE1.U40 MODULE1.U42 MODULE1.U43 MODULE1.U46 MODULE1.V1 MODULE1.V2 MODULE1.V3 MODULE1.V4 MODULE1.V5 MODULE1.V6 MODULE1.V7 MODULE1.V8 MODULE1.V9 MODULE1.V10 MODULE1.V11 MODULE1.V12 MODULE1.V13 MODULE1.V14 MODULE1.V15 MODULE1.V16 MODULE1.V17 MODULE1.V18 MODULE1.V19 MODULE1.V20 MODULE1.V32 MODULE1.V33 MODULE1.V34 MODULE1.V35 MODULE1.V36 MODULE1.V37 MODULE1.V41 MODULE1.V44 MODULE1.W1 MODULE1.W2 MODULE1.W3 MODULE1.W4 MODULE1.W5 MODULE1.W6 MODULE1.W7 MODULE1.W8 MODULE1.W9 MODULE1.W10 MODULE1.W11 MODULE1.W12 MODULE1.W13 MODULE1.W14 MODULE1.W15 MODULE1.W16 MODULE1.W17 MODULE1.W18 MODULE1.W19 MODULE1.W32 MODULE1.W33 MODULE1.W34 MODULE1.W35 MODULE1.W36 MODULE1.W37 MODULE1.W44 MODULE1.W45 MODULE1.W46 MODULE1.Y1 MODULE1.Y2 MODULE1.Y3 MODULE1.Y4 MODULE1.Y5 MODULE1.Y6 MODULE1.Y7 MODULE1.Y8 MODULE1.Y9 MODULE1.Y10 MODULE1.Y11 MODULE1.Y12 MODULE1.Y13 MODULE1.Y14 MODULE1.Y15 MODULE1.Y16 MODULE1.Y17 MODULE1.Y32 MODULE1.Y33 MODULE1.Y34 MODULE1.Y35 MODULE1.Y36 MODULE1.Y37 MODULE1.Y44 PB1.1 PB1.2 PB1.5 PB2.2 PB2.MNT Q3.1 Q3.4 Q4.1 Q4.4 Q7.1 Q7.2 Q7.4 Q7.6 R8.1 R9.1 R10.1 R11.1 R16.1 R17.1 R18.1 R19.1 R20.1 R24.1 R27.1 R28.1 R29.1 R30.1 R44.1 R45.1 R46.1 R47.1 R48.1 R49.1 R50.1 R51.1 R52.1 R53.1 R54.1 R55.1 R56.1 R77.1 R78.1 R79.1 R80.1 R81.1 R82.1 R83.1 R88.1 R89.1 R92.2 R94.1 R95.1 R109.1 R116.1 R119.1 R120.1 R128.2 R130.2 R131.1 R137.1 R141.1 R142.1 R146.2 R147.2 R149.2 R154.1 R156.1 R167.1 R172.1 R173.2 R179.1 R180.1 R182.1 R183.1 R184.1 R192.2 R193.2 R209.1 R215.2 R221.1 R232.1 R238.1 R241.1 R243.1 R247.2 R249.2 R269.1 R288.2 R289.2 R290.2 R293.1 R294.1 R299.1 R300.1 R301.1 R302.1 R305.1 R306.1 R307.1 R308.1 R309.1 R315.1 R316.1 R323.1 R324.1 R325.2 R338.1 R340.1 R342.1 R352.1 R354.1 R355.1 R356.1 R357.1 R359.1 R360.1 R389.2 R390.2 R391.2 R395.2 R396.1 R400.1 R426.1 R427.1 R428.1 R429.1 R436.2 R437.2 R449.2 R450.2 R460.1 R461.1 R466.1 R467.1 R468.1 R472.1 R473.1 R474.1 R481.1 R483.1 R499.1 R500.1 R511.1 TP30.X TP36.X TP78.X TP79.X TP80.X TP81.X TP92.X TP_FLASH_SAIL_GND.X U1.57 U2.B3 U2.C1 U2.E5 U3.A1 U3.A15 U3.E3 U3.E5 U3.E11 U3.F8 U3.G8 U3.G12 U3.H6 U3.H7 U3.H8 U3.H9 U3.H10 U3.J3 U3.J8 U3.K3 U3.K4 U3.K8 U3.L5 U3.L11 U3.P12 U3.R1 U3.R15 U4.5 U4.7 U5.13 U5.53 U6.15 U6.18 U6.37 U6.41 U7.2 U7.9 U8.3 U9.3 U10_1.3 U10_1.4 U10_1.39 U10_1.40 U10_1.41 U10_1.42 U10_1.43 U10_2.3 U10_2.4 U10_2.39 U10_2.40 U10_2.41 U10_2.42 U10_2.43 U10_3.3 U10_3.4 U10_3.39 U10_3.40 U10_3.41 U10_3.42 U10_3.43 U11.7 U11.8 U11.11 U11.12 U11.21 U12.6 U12.17 U12.20 U12.23 U12.26 U12.32 U12.35 U12.38 U12.41 U12.62 U12.68 U12.71 U12.74 U12.77 U12.79 U12.80 U12.81 U12.82 U12.83 U12.84 U12.85 U12.86 U12.87 U12.88 U12.89 U12.90 U12.91 U12.92 U12.93 U12.94 U12.96 U12.97 U12.98 U12.99 U12.100 U12.101 U12.102 U12.103 U12.104 U12.105 U12.106 U12.107 U12.108 U13.7 U13.8 U13.11 U13.12 U13.21 U14.7 U14.8 U14.11 U14.12 U14.21 U15.2 U16.4 U17.4 U18.1 U19.3 U20.3 U21_1.6 U21_2.6 U21_3.6 U21_4.6 U21_5.6 U22.B2 U22.B3 U22.B5 U22.B6 U22.C7 U22.E1 U22.E7 U22.F1 U22.F7 U23.2 U23.11 U23.19 U23.31 U23.37 U23.49 U24.A53 U24.B20 U24.C1 U24.C2 U24.C3 U24.C4 U25.3 U26.8 U26.13 U27_1.2 U27_2.2 U27_3.2 U27_4.2 U27_5.2 U27_6.2 U28.2 U29.2 U30.3 U30.7 U31.3 U32.3 U33_1.11 U33_1.21 U33_2.11 U33_2.21 U33_3.11 U33_3.21 U33_4.11 U33_4.21 U33_5.11 U33_5.21 U34.AB34 U34.B18 U34.B22 U34.GND U34.V34 U35.3 U36.3 Y1.2 Y1.4 Y2.2 Y2.4 Y3.2 Y3.4 | length 708
  TOP_L1 w0.084: v1(37.082,76.349) v6(37.082,77.582) ; U6.37@87.075,77.265 87.462,77.265 v1(87.497,77.299)
  TOP_L1 w0.086: v1(57.182,138.491) U10_2.3@57.264,138.409 ; U10_2.4@57.6,138.409 v1(57.682,138.491)
  TOP_L1 w0.1: v1(12.9,66.3) U33_4.11@13.35,66.3 ; v1(18.025,65.875) C174_4.1@18.45,65.875 ; v1(18.025,67.275) C173_4.1@18.45,67.275 ; v1(19.168,6.669) D82.1@19.44,6.669 D82.1@19.465,6.669 ; v1(20.55,6.624) D81.1@20.766,6.624 D81.1@20.791,6.624 ; D80.1@22.591,6.624 22.823,6.856 v1(22.823,6.896) ; v1(27.4,66.3) U33_3.11@27.85,66.3 ; v1(32.525,65.875) C174_3.1@32.95,65.875 ; v1(32.525,67.275) C173_3.1@32.95,67.275 ; v1(36.4,66.3) U33_2.11@36.85,66.3 ; U34.V34@37.421,32.849 v1(37.661,32.849) ; v1(41.525,65.875) C174_2.1@41.95,65.875 ; v1(41.525,67.275) C173_2.1@41.95,67.275 ; U22.B6@76.075,58 76.273,57.802 v1(76.273,57.784) ; U22.B5@76.075,58.5 v1(76.282,58.292) ; v1(78.324,152.132) D10_2.1@78.324,152.66 ; v1(80.324,152.132) D15_2.1@80.324,152.66
  TOP_L1 w0.109: v2(33.911,154.056) v1@33.965,154.11 ; v1@35.341,152.516 v4(35.395,152.57)
  TOP_L1 w0.127: C333.2@13.392,46.7 v1(14.122,46.7) ; Q7.4@21.65,10.2 v1(21.65,10.933) ; v1(33.832,75.649) R156.1@33.832,74.949 33.832,74.629 v2(34.086,74.376) 34.086,74.343 34.211,74.217 34.211,73.534 U19.3@34.232,73.513 ; U27_2.2@35.191,24.224 35.902,24.224 36.027,24.349 v1(36.341,24.349) ; 43.374,139.371 43.382,139.379 ; v1(43.382,138.786) 43.382,139.379 ; U10_1.42@44.182,139.391 43.393,139.391 43.382,139.379 ; U10_1.41@44.182,139.891 43.419,139.891 43.382,139.928 ; U10_1.40@44.182,140.391 43.39,140.391 43.382,140.383 ; U10_1.39@44.182,140.891 43.691,140.891 43.382,140.582 43.382,140.383 ; U10_2.42@55.782,139.391 54.969,139.391 v1(54.951,139.409) 54.951,139.897 ; U10_2.41@55.782,139.891 54.957,139.891 54.951,139.897 ; U10_2.40@55.782,140.391 54.96,140.391 54.951,140.4 ; U10_2.39@55.782,140.891 55.1,140.891 54.951,140.742 54.951,140.4 ; 66.569,139.888 66.572,139.891 U10_3.41@67.382,139.891 ; U10_3.42@67.382,139.391 66.915,139.391 66.822,139.484 v1(66.551,139.484) 66.551,140.652 66.79,140.891 U10_3.39@67.382,140.891 ; 43.382,139.379 43.382,139.928 ; 43.382,139.928 43.382,140.383 ; 54.951,139.897 54.951,140.4
  TOP_L1 w0.15: v1@1.179,46.26 1.425,46.506 1.425,46.512 1.812,46.899 PB1.2@1.863,46.899 ; R340.1@1.74,77.319 v1(2.25,77.319) ; v5(1.879,46.254) 1.879,46.882 PB1.2@2.15,47.153 2.579,46.724 v5(2.579,46.254) ; v1(9.768,72.43) R338.1@9.768,72.961 ; v1(11.05,15.841) D63.1@11.385,15.841 D63.1@11.41,15.841 ; v1(11.05,20.921) D62.1@11.385,20.921 D62.1@11.41,20.921 ; v1(11.05,23.461) D61.1@11.385,23.461 D61.1@11.41,23.461 ; U27_4.2@11.468,71.686 11.468,72.33 11.743,72.605 v1(11.743,72.936) ; v1(15,10.2) Q4.4@15.4,10.2 ; Q4.1@16.9,12 17.373,12 v1(17.684,12.311) ; U31.3@17.26,71.79 v1(17.26,72.34) ; v1(18.26,73.72) U32.3@18.26,74.27 ; v1(19.308,8.68) 19.327,8.699 19.327,8.817 19.75,9.24 C70.2@19.75,9.265 ; D67.1@23.11,18.381 D67.1@23.135,18.381 v1(23.47,18.381) ; D66.1@23.11,20.421 D66.1@23.135,20.421 v1(23.47,20.421) ; D65.1@23.11,21.421 D65.1@23.135,21.421 v1(23.47,21.421) ; D64.1@23.11,22.221 D64.1@23.135,22.221 v1(23.47,22.221) ; J6.20@31.23,61.75 31.23,60.794 v2(31.557,60.467) ; v1(32.815,33.79) 32.824,33.799 D41.1@32.824,34.25 D41.1@32.824,34.275 ; v1(32.821,36.438) 32.824,36.441 D35.1@32.824,36.75 D35.1@32.824,36.775 ; D42.1@32.824,35.575 D42.1@32.824,35.6 32.824,35.908 v1(32.828,35.912) ; D33.1@32.824,38.575 D33.1@32.824,38.6 32.824,38.908 v1(32.828,38.912) ; v2(33.469,26) 33.476,26.007 D40.1@33.476,26.664 ; C94.1@36.332,73.148 v1(36.332,73.668) ; U35.3@38.062,73.513 v1(38.062,74.078) ; v2(43.972,25.867) 44.137,25.702 44.809,25.702 ; C278.1@44.342,73.148 45.308,73.148 v2(45.325,73.165) 45.349,73.141 U21_4.6@46.2,73.141 ; v1(45.7,70.464) R323.1@45.7,70.862 ; R315.1@45.8,75.566 v1(45.8,76.041) ; v1(50.324,151.943) D10_3.1@50.324,152.66 ; v1(50.501,73.169) U21_2.6@51.139,73.169 ; v1(52.324,151.943) D15_3.1@52.324,152.66 ; C266.1@57.213,15.729 57.223,15.719 57.546,15.719 v1(57.555,15.71) 57.582,15.71 57.713,15.579 v1(57.963,15.579) ; C263.1@57.263,13.329 57.263,13.016 57.333,12.947 v1(57.333,12.92) ; C279.1@57.963,13.379 58.181,13.597 58.233,13.597 v1(58.252,13.616) ; v1(58.402,15.734) 58.708,15.734 C275.1@58.713,15.729 ; v1(58.405,13.326) 58.76,13.326 C272.1@58.763,13.329 ; v2(66,27.415) 66.315,27.1 69.311,27.1 69.431,26.98 69.511,26.98 v2(69.53,26.961) 70.043,26.961 v1(70.406,27.324) ; v1(66.972,147.95) 67.85,147.95 ; v2(74.436,143.149) 74.436,143.554 ; v2(75.636,143.149) 75.925,143.438 ; v2(78.201,56.669) 78.22,56.65 78.22,56.523 v1(78.424,56.319) ; v2(78.201,57.069) 78.22,57.088 78.22,57.204 v1(78.424,57.409) ; v6(78.8,77) 78.922,77 79.105,77.183 79.183,77.183 79.265,77.265 U6.18@81.125,77.265 ; v6(80.2,79) 80.735,78.465 U6.15@81.125,78.465 ; v1(81.002,80.316) R94.1@81.3,80.316 ; v6(81.723,42.716) 81.321,42.314 81.321,40.873 81.738,40.455 82.653,40.455 v2(83.104,40.004) ; C60.1@83.1,80.316 v1(83.1,80.615) ; C54.1@84.3,80.316 v1(84.3,80.615) ; C56.1@85.5,80.316 v1(85.5,80.615) ; R450.2@86.601,69.985 86.601,69.666 v2(86.804,69.463) ; v1(88.005,69.463) 88.211,69.668 R449.2@88.211,69.985
  TOP_L1 w0.2: R215.2@1.5,130.515 v6(1.5,131.065) 2.55,131.065 U29.2@2.7,130.915 ; v1(1.765,79.294) 2.129,79.294 2.404,79.019 U27_3.2@3.015,79.019 ; v1(2.4,107.24) 2.475,107.165 U11.21@3.725,107.165 ; v2(5.184,83.202) C338.1@5.79,83.202 ; C321.2@7.27,89.816 7.282,89.804 8.138,89.804 v6(8.15,89.792) ; C100.2@7.27,96.116 v6(8.092,96.116) ; C320.2@7.27,103.965 v6(8.092,103.965) ; C90.2@7.27,110.365 v6(8.092,110.365) ; C319.2@7.27,115.265 v6(8.092,115.265) ; C79.2@7.27,121.665 v6(8.092,121.665) ; U25.3@7.505,85.202 v1(7.505,85.591) ; v6(8.019,78.483) 8.128,78.483 8.277,78.633 8.513,78.633 C116.2@8.683,78.802 ; C187.1@10.725,81.073 11.657,80.141 v1(12.168,80.141) ; v6(11.282,66.741) 11.282,66.671 11.53,66.423 C176_4.2@11.53,65.95 ; U21_3.6@11.936,148.275 v1(12.475,148.275) ; v1@12.168,79.472 12.168,79.216 12.193,79.191 U16.4@12.418,79.191 ; v6(13.124,153.477) J3_1.1@13.124,154.475 ; v6(14.064,143.558) U15.2@15,143.558 ; D6_1.3@14.624,151.585 D6_1.3@14.624,151.956 D6_1.3@14.624,152.337 ; D6_1.8@14.624,152.984 v6(14.624,153.477) J3_1.4@14.624,154.475 ; v6(16.124,153.477) J3_1.7@16.124,154.475 ; C306.1@16.16,74.735 16.16,74.54 v1(16.36,74.34) ; v2(17.617,7.423) C205.1@17.617,7.724 ; D7_1.3@17.624,151.585 D7_1.3@17.624,151.956 D7_1.8@17.624,152.337 ; D7_1.8@17.624,152.984 v6(17.624,153.477) J3_1.10@17.624,154.475 ; v6(19.124,153.477) J3_1.13@19.124,154.475 ; C305.1@19.16,71.325 v1(19.16,71.675) ; D8_1.3@20.624,151.585 D8_1.3@20.624,151.956 D8_1.8@20.624,152.337 ; D8_1.8@20.624,152.984 v6(20.624,153.477) J3_1.16@20.624,154.475 ; v6(22.124,153.477) J3_1.19@22.124,154.475 ; v1(22.755,24.925) J10.1@23.726,24.925 ; v1(22.755,25.425) J10.3@23.726,25.425 ; v1(22.755,26.925) J10.9@23.726,26.925 24.861,26.925 24.952,27.015 24.952,27.394 v5(24.961,27.403) ; v1(22.755,28.425) J10.15@23.726,28.425 ; v1(22.755,29.925) J10.21@23.726,29.925 ; v1(22.755,31.425) J10.27@23.726,31.425 ; v1(22.755,32.925) J10.33@23.726,32.925 ; v1(22.755,34.425) J10.39@23.726,34.425 ; v1(22.755,35.925) J10.45@23.726,35.925 ; v1(22.755,37.425) J10.51@23.726,37.425 25.425,37.425 v5(25.7,37.7) ; v1(22.755,38.925) J10.57@23.726,38.925 ; J10.71@23.726,42.425 v2(25.025,42.425) ; J10.75@23.726,43.425 24.98,43.425 v2(25.082,43.323) ; J10.32@31.276,32.675 31.28,32.678 32.817,32.678 32.821,32.682 32.821,33.502 32.151,34.172 31.529,34.172 31.526,34.175 J10.38@31.276,34.175 ; D27.1@33.252,42.175 D27.1@33.277,42.175 v1(33.672,42.175) 35.023,42.175 C227.1@35.103,42.255 34.484,42.875 v1(33.872,42.875) C224.1@33.402,42.875 ; v6(41.124,153.477) J3_3.1@41.124,154.475 ; D6_3.8@42.624,152.984 v6(42.624,153.477) J3_3.4@42.624,154.475 ; v6(44.124,153.477) J3_3.7@44.124,154.475 ; v1@45.432,66.55 U21_1.6@46.2,66.55 ; D7_3.8@45.624,152.984 J3_3.10@45.624,154.475 v6(45.624,155.691) ; J3_3.13@47.124,154.475 47.124,155.691 ; D8_3.8@48.624,152.984 v6(48.624,153.477) J3_3.16@48.624,154.475 ; 56.52,30.999 58.1,30.999 ; 65.936,25.999 JSPI.6@67.028,25.999 ; JSPI.6@67.627,25.4 JSPI.6@67.028,25.999 ; v1(68.091,32.249) C204.1@68.516,32.249 ; v4(68.091,32.849) C199.1@68.516,32.849 ; v4(68.116,35.849) C195.1@68.541,35.849 ; v1(68.516,33.624) C198.1@68.516,34.049 ; v1(69.36,25.622) 68.984,25.999 JSPI.6@67.028,25.999 ; v2(69.862,28.795) 70.058,28.599 U24.C4@70.341,28.599 ; U24.C3@70.341,37.099 70.348,37.092 70.598,37.092 v5(70.605,37.085) ; C124.1@70.556,21.334 70.564,21.326 70.564,20.776 v6@70.572,20.768 ; v6(70.588,20.784) 71.04,21.237 71.04,21.792 71.158,21.909 U17.4@71.531,21.909 ; D6_2.8@70.624,152.603 v1(70.624,153.539) J3_2.4@70.624,154.475 ; R147.2@70.631,18.434 70.631,17.81 v6(70.931,17.51) ; v1(71.082,92.236) 71.432,91.886 v3(71.432,91.636) ; MODULE1.BB14@71.232,97.036 71.582,96.686 v5(71.582,96.436) ; MODULE1.BB18@71.282,101.836 71.632,101.486 v5(71.632,101.236) ; v6(71.631,17.709) C127.2@71.631,18.474 ; J3_2.7@72.124,154.475 v6(72.124,155.691) ; v1(72.282,93.436) 72.632,93.086 v3(72.632,92.836) ; MODULE1.BC15@72.432,98.236 72.782,97.886 v5(72.782,97.636) ; v1@72.569,4.047 v1@75.569,4.047 ; v2(72.982,96.436) 72.982,96.186 MODULE1.BD13@73.332,95.836 ; v3(72.982,101.236) 72.982,100.986 MODULE1.BD17@73.332,100.636 ; v5(73.132,91.636) 73.132,91.386 v1(73.482,91.036) ; v1(73.482,94.636) 73.832,94.286 v1(73.832,94.036) ; v1(73.482,104.236) 73.832,103.886 v5(73.832,103.636) ; D7_2.8@73.624,152.984 v6(73.624,153.477) J3_2.10@73.624,154.475 ; MODULE1.BD16@73.632,99.436 73.982,99.086 v2(73.982,98.836) ; U24.B20@73.766,36.499 73.766,35.954 v6(73.731,35.918) 73.731,33.709 v3(74.591,32.849) ; v6(73.981,20.959) C123.1@73.981,21.659 ; v5(74.182,97.636) 74.182,97.386 MODULE1.BE14@74.532,97.036 ; v1(74.332,92.836) 74.332,92.586 v1(74.682,92.236) ; v1(74.682,95.836) 75.032,95.486 v5(75.032,95.236) ; MODULE1.BE17@74.832,100.636 75.182,100.286 v5(75.182,100.036) ; C19.1@74.856,11.234 75.189,11.234 75.396,11.027 v6(75.396,10.987) ; v6(75.124,153.477) J3_2.13@75.124,154.475 ; v1(75.382,98.836) 75.382,98.586 MODULE1.BF15@75.732,98.236 ; v3(75.532,94.036) 75.532,93.786 v1(75.882,93.436) ; v1(75.532,103.636) 75.532,103.386 v1(75.882,103.036) ; D8_2.8@76.624,152.984 v6(76.624,153.477) J3_2.16@76.624,154.475 ; v6(78.124,153.477) J3_2.19@78.124,154.475 ; v5(78.841,28.174) U24.C1@78.841,28.599 ; U24.C2@78.841,37.099 v1(79.266,37.099) ; v1(80,33.25) 81.779,33.25 81.829,33.2 82.05,33.2 ; R192.2@80.666,28.559 80.911,28.559 80.996,28.643 v4(81.009,28.643) ; C184.1@80.666,29.249 v5(81.091,29.249) ; C206.1@80.666,30.449 v2(81.091,30.449) ; C188.1@80.666,31.049 v2(81.091,31.049) ; C189.1@80.666,32.249 v5(81.091,32.249) ; C185.1@80.666,34.249 80.721,34.304 80.721,34.319 80.863,34.46 81.083,34.46 v1(81.09,34.453) ; v6(81.723,42.716) 82.711,42.716 D78.8@82.752,42.675 ; D78.3@83.399,42.675 v6(84.298,42.675) ; v6(83.402,63.623) D16.8@83.402,64.476 ; D16.3@83.402,65.123 v6(83.402,65.976) ; v6(87.002,63.623) D13.8@87.002,64.476 ; D13.3@87.002,65.123 v6(87.002,65.976) ; v6(89.167,73.229) D73.8@90.021,73.229 ; v6(89.167,76.229) D72.8@90.021,76.229 ; v6(89.168,69.859) D74.8@90.021,69.859 ; v6(89.168,79.536) D75.8@90.021,79.536 ; D74.3@90.668,69.859 v6(91.521,69.859) ; D75.3@90.668,79.536 v6(91.521,79.536) ; v6(92.415,77.988) 92.415,77.979 92.648,77.746 J1.A12@92.648,77.605 ; v6(92.601,71.56) 92.651,71.61 92.651,72.079 92.676,72.104 J1.A1@92.876,72.104 ; J1.B12@94.376,71.854 94.883,71.854 v6@95.094,71.643 ; J1.B1@94.376,77.354 94.804,77.354 95.306,77.856 v6(95.306,78.122) ; v6@95.094,71.691 v6@95.094,71.643 ; v6(95.181,71.556) v6@95.094,71.643 ; 95.4,30.753 v1(95.4,31.652) ; v1(95.4,32.299) 95.4,32.9 95.6,33.1 96.75,33.1 ; 98.3,30.753 v1(98.3,31.652)
  TOP_L1 w0.25: 80.572,35.779 80.572,37.522 80.7,37.65
  TOP_L1 w0.3: 11.737,79.654 12,79.654 v1(12.168,79.486) ; v2(19.106,28.225) D28.8@20.255,28.225 D28.3@20.902,28.225 ; v5(19.106,31.025) D29.8@20.255,31.025 D29.3@20.902,31.025 ; v3(19.106,33.825) D30.8@20.255,33.825 D30.3@20.902,33.825 ; v5(19.106,36.625) D31.8@20.255,36.625 D31.3@20.902,36.625 ; v1@34,66.4 34.45,65.95 C176_2.2@35.03,65.95
  TOP_L1 w0.4: v6(5.591,65.05) C221.1@6.67,65.05 ; v6(8.894,87.985) 8.889,87.981 8.251,87.981 7.9,88.332 C99.2@7.9,88.366 7.9,88.781 v6(8.9,88.781) ; v6(8.9,111.38) 7.9,111.38 C88.2@7.9,111.765 7.9,112.18 v6(8.9,112.18) ; v6(8.9,113.48) 7.9,113.48 C89.2@7.9,113.865 7.9,114.28 v6(8.9,114.28) ; v6(8.9,97.181) 7.9,97.181 C98.2@7.9,97.566 7.9,97.981 v6(8.9,97.981) ; v6(8.9,99.98) 7.9,99.98 C76.2@7.9,100.365 7.9,100.78 v6(8.9,100.78) ; v6(8.9,101.98) 7.9,101.98 C87.2@7.9,102.365 7.9,102.78 v6(8.9,102.78) ; v6(8.9,122.68) 7.9,122.68 C78.2@7.9,123.065 7.9,123.48 v6(8.9,123.48) ; v6(8.9,124.68) 7.9,124.68 C77.2@7.9,125.065 7.9,125.48 v6(8.9,125.48) ; v6(9.618,81.826) 10.618,81.826 C187.1@10.618,81.441 10.618,81.073 10.571,81.026 9.676,81.026 v6(9.639,81.063) ; v6(9.618,82.926) 10.618,82.926 C120.1@10.618,83.341 10.618,83.726 v6(9.618,83.726) ; v6(9.727,87.514) 9.765,87.475 10.567,87.475 C255.1@10.605,87.514 ; v6@9.765,86.807 C255.1@10.567,86.807 ; v6(10.818,75.026) 11.818,75.026 C117.1@11.818,75.441 11.818,75.826 v6(10.818,75.826) ; v6(16.625,87.781) 15.625,87.781 C223.1@15.625,88.166 15.625,88.581 v6(16.625,88.581) ; v6(16.625,97.381) 15.625,97.381 C276.1@15.625,97.766 15.625,98.181 v6(16.625,98.181) ; v6(16.625,101.78) 15.625,101.78 C313.1@15.625,102.165 15.625,102.58 v6(16.625,102.58) ; v6(16.625,111.38) 15.625,111.38 C317.1@15.625,111.765 15.625,112.18 v6(16.625,112.18) ; v6(16.625,113.48) 15.625,113.48 C315.1@15.625,113.865 15.625,114.28 v6(16.625,114.28) ; v6(16.625,122.88) 15.625,122.88 C316.1@15.625,123.265 15.625,123.68 v6(16.625,123.68) ; v6(17.685,98.566) 17.685,97.566 C103.1@18.1,97.566 18.485,97.566 v6(18.485,98.566) ; v6(17.685,123.939) 17.685,123.065 C81.1@18.1,123.065 18.485,123.065 v6(18.485,123.939) ; v6(17.715,87.366) 17.715,88.366 C104.1@18.1,88.366 18.515,88.366 v6(18.515,87.366) ; v6(17.715,101.565) 17.715,102.565 C312.1@18.1,102.565 18.515,102.565 v6(18.515,101.565) ; v6(20.417,3.866) J13.1@20.417,5.024 ; 66.866,19.109 66.866,20.109 C125.1@67.281,20.109 67.598,19.792 67.598,19.4 v6(67.923,19.075) ; v6(68.766,19.109) 68.766,20.109 C311.1@69.181,20.109 ; v6(69.55,18.841) 69.512,18.879 69.512,19.778 C311.1@69.181,20.109 ; v6(70.588,20.784) 70.572,20.768 70.204,20.4 69.5,20.4 69.209,20.109 C311.1@69.181,20.109 ; v6(74.866,20.809) 74.866,21.809 C122.1@75.281,21.809 v6(76.473,21.809) ; v6(82.384,7.06) C66.2@83.484,7.06 ; C318.1@17.685,111.765 v6(17.685,112.815) 17.685,113.865 C82.1@18.1,113.865 18.515,113.865 v6(18.515,112.815) 18.515,111.765 C318.1@18.1,111.765 C318.1@17.685,111.765
  TOP_L1 w0.5: v6(6.368,81.611) 6.765,81.214 C222.1@6.765,80.519 ; J6.9@18.53,56.25 19.039,55.741 v6(19.882,55.741) ; C83.1@21.3,140.95 C38.1@25.6,140.95 ; C177.1@25.6,142.8 C38.1@25.6,140.95 ; C178.1@27.3,140.95 C38.1@25.6,140.95 ; JFAN.4@29,71.85 v6(29,75.4) ; C227.1@35.103,42.255 35.103,44.002 C226.1@35.276,44.175 ; C200.1@83.911,27.409 84.2,27.12 v6(84.2,26)
  TOP_L1 w0.7: C294.1@6.75,141.3 6.75,141.85 v6(7.2,142.3)
  L2 w0.15: v3(56.504,143.34) 57.116,142.931 ; 74.436,142.762 v2(74.436,143.149) 74.436,143.536 74.5,143.6 ; 75.443,142.709 v2(75.636,143.149) ; 78.201,56.401 v2(78.201,56.669) ; v2(78.201,57.069) 78.201,57.337
  L2 w1.3: 89,119.5 J5.2@91.748,119.5 ; 91.748,122.248 J5.2@91.748,119.5 ; 91.8,114.8 J5.3@94.548,114.8 ; 94.496,119.5 J5.2@91.748,119.5 ; 94.548,112.052 J5.3@94.548,114.8 ; 94.548,117.548 J5.3@94.548,114.8 ; 97.296,114.8 J5.3@94.548,114.8
  L3 w0.1: v2(9.11,115.75) v5(9.11,116.11)
  L3 w0.127: v5(34,66.791) 34,66.4 v1(34.007,66.4)
  L3 w0.15: 22.2,109 23.293,109.463 ; 23.897,114.378 25.981,114.378 ; v5(35.56,31.993) 36.496,31.993 36.601,32.099 ; v1(35.96,33.581) 35.974,33.581 36.444,33.11 36.444,33.099 ; 37.546,34.334 38.073,34.334 38.452,33.955 38.724,33.955 ; 37.575,24.937 40.678,24.937 41.138,24.478 ; v1(37.832,34.67) 38.046,34.885 38.214,34.885 38.246,34.917 38.557,34.917 38.578,34.896 38.602,34.896 38.613,34.885 39.07,34.885 39.115,34.84 ; 39.629,30.429 39.664,30.394 39.664,29.557 39.8,29.421 39.8,29.4 ; v1(58.082,133.636) 58.375,134.252 58.397,134.298 58.397,135.924 58.482,136.009 v2(58.482,136.036) ; 66.458,3.581 66.5,3.623 67.337,3.623 ; 70.791,28.874 71.417,29.5 72.185,29.5 72.222,29.463 72.232,29.463 72.296,29.399 72.501,29.399 72.7,29.2 ; v1(73.766,29.639) 74.378,29.027 74.378,28.84 ; v2(74.436,143.149) 74.436,143.547 cw(c74.653,143.547) 74.5,143.7 ; 77.337,102.914 77.69,102.914 78.056,102.548 ; 77.701,37.3 77.798,37.3 78.295,37.797 78.295,38.195 ; 78.201,56.452 v2(78.201,56.669) ; v2(78.201,57.069) 78.201,57.286 ; 90.7,77.5 90.7,78.6
  L3 w0.2: v5(44.428,29.177) 44.428,29.238 v2(44.802,29.611) ; v2(45.27,29.089) 45.475,29.089 v5(45.673,28.891) ; v2(64.715,6.365) v5(65.023,6.365) ; v2(64.721,4.709) v3(65.03,4.709) ; 66.456,3.583 66.458,3.581 ; 72.79,105.18 72.79,103.127 74.07,101.847 74.421,101.847 ; 77.844,34.776 78.167,35.099 78.42,35.351
  L3 w0.25: v5(7.19,91.309) 7.2,91.299 v2(7.651,91.299) ; v5(7.19,94.622) 7.2,94.632 v1(7.651,94.632) ; v5(7.19,105.509) 7.2,105.499 v2(7.651,105.499) ; v5(7.19,108.821) 7.2,108.831 v1(7.651,108.831) ; v5(7.19,116.809) 7.2,116.799 v1(7.651,116.799) ; v5(7.19,120.121) 7.2,120.131 v2(7.651,120.131) ; v5(7.547,92.096) 7.551,92.092 7.551,91.796 v1(7.662,91.685) ; v5(7.547,93.835) 7.551,93.84 7.551,94.135 v1(7.662,94.246) ; v5(7.547,106.295) 7.551,106.291 7.551,105.995 v1(7.662,105.885) ; v5(7.547,108.035) 7.551,108.039 7.551,108.335 v1(7.662,108.445) ; v5(7.547,117.595) 7.551,117.591 7.551,117.295 v1(7.662,117.185) ; v5(7.547,119.335) 7.551,119.339 7.551,119.635 v2(7.662,119.745) ; v5(7.612,90.384) 7.614,90.385 v1(7.614,90.797) ; v5(7.612,95.547) 7.614,95.546 v2(7.614,95.134) ; v5(7.612,104.583) 7.614,104.585 v2(7.614,104.996) ; v5(7.612,109.747) 7.614,109.745 v2(7.614,109.334) ; v5(7.612,115.883) 7.614,115.885 v1(7.614,116.296) ; v5(7.612,121.047) 7.614,121.045 v2(7.614,120.634) ; v5(8.112,92.131) 8.122,92.121 8.122,91.725 v1(8.162,91.685) ; v5(8.112,93.8) 8.122,93.81 8.122,94.206 v2(8.162,94.246) ; v5(8.112,106.33) 8.122,106.32 8.122,105.925 v2(8.162,105.885) ; v5(8.112,108) 8.122,108.01 8.122,108.405 v2(8.162,108.445) ; v5(8.112,117.63) 8.122,117.62 8.122,117.225 v2(8.162,117.185) ; v5(8.112,119.3) 8.122,119.31 8.122,119.705 v2(8.162,119.745) ; v1(8.127,90.805) 8.254,90.805 8.499,90.56 v5(8.535,90.56) ; v1(8.127,95.126) 8.254,95.126 8.499,95.371 v5(8.535,95.371) ; v2(8.127,105.005) 8.254,105.005 8.499,104.759 v5(8.535,104.759) ; v1(8.127,109.325) 8.319,109.517 8.495,109.517 v5(8.524,109.546) ; v1(8.127,116.305) 8.254,116.305 8.499,116.059 v5(8.535,116.059) ; v1(8.127,120.625) 8.254,120.625 8.499,120.871 v5(8.535,120.871) ; v1(8.129,91.308) 8.177,91.26 8.379,91.26 8.414,91.226 8.646,91.226 v5(8.675,91.198) ; v1(8.129,94.623) 8.177,94.671 8.379,94.671 8.414,94.705 8.646,94.705 v5(8.675,94.734) ; v2(8.129,105.507) 8.177,105.46 8.379,105.46 8.414,105.426 8.646,105.426 v5(8.675,105.397) ; v2(8.129,108.823) 8.177,108.87 8.379,108.87 8.414,108.904 8.646,108.904 v5(8.675,108.933) ; v2(8.129,116.807) 8.177,116.76 8.379,116.76 8.414,116.726 8.646,116.726 v5(8.675,116.697) ; v1(8.129,120.123) 8.177,120.17 8.379,120.17 8.414,120.204 8.646,120.204 v5(8.675,120.233) ; v2(8.662,91.685) 8.723,91.746 v5(8.723,92.092) ; v1(8.662,94.246) 8.723,94.185 v5(8.723,93.839) ; v1(8.662,105.885) 8.723,105.946 v5(8.723,106.292) ; v1(8.662,108.445) 8.723,108.384 v5(8.723,108.038) ; v1(8.662,117.185) 8.723,117.246 v5(8.723,117.592) ; v1(8.662,119.745) 8.723,119.684 v5(8.723,119.338)
  L3 w1.3: 89,119.5 J5.2@91.748,119.5 ; 91.748,116.752 J5.2@91.748,119.5 ; 91.748,122.248 J5.2@91.748,119.5 ; 91.8,114.8 J5.3@94.548,114.8 ; 94.496,119.5 J5.2@91.748,119.5 ; 94.548,112.052 J5.3@94.548,114.8 ; 94.548,117.548 J5.3@94.548,114.8 ; 97.296,114.8 J5.3@94.548,114.8
  L4 w1.3: 89,119.5 J5.2@91.748,119.5 ; 91.748,116.752 J5.2@91.748,119.5 ; 91.748,122.248 J5.2@91.748,119.5 ; 91.8,114.8 J5.3@94.548,114.8 ; 94.496,119.5 J5.2@91.748,119.5 ; 94.548,112.052 J5.3@94.548,114.8 ; 94.548,117.548 J5.3@94.548,114.8 ; 97.296,114.8 J5.3@94.548,114.8
  L7 w1.3: 89,119.5 J5.2@91.748,119.5 ; 91.748,116.752 J5.2@91.748,119.5 ; 91.748,122.248 J5.2@91.748,119.5 ; 91.8,114.8 J5.3@94.548,114.8 ; 94.496,119.5 J5.2@91.748,119.5 ; 94.548,112.052 J5.3@94.548,114.8 ; 94.548,117.548 J5.3@94.548,114.8 ; 97.296,114.8 J5.3@94.548,114.8
  L8 w0.15: 20.732,148.832 22.032,148.832 22.1,148.9 ; 83.837,72.161 83.837,70.177 84.234,69.78
  L8 w0.2: 0.6,105.011 0.6,106.667 ; 0.6,116.695 0.6,106.667 ; 1.723,106.243 1.516,106.243 1.168,106.591 0.676,106.591 0.6,106.667 ; 63.705,4.123 64.282,3.545 67.55,3.545
  L8 w1.3: 89,119.5 J5.2@91.748,119.5 ; 91.748,116.752 J5.2@91.748,119.5 ; 91.748,122.248 J5.2@91.748,119.5 ; 91.8,114.8 J5.3@94.548,114.8 ; 94.496,119.5 J5.2@91.748,119.5 ; 94.548,112.052 J5.3@94.548,114.8 ; 94.548,117.548 J5.3@94.548,114.8 ; 97.296,114.8 J5.3@94.548,114.8
  L9 w0.3: v3(26.062,44.349) v4(26.258,44.153)
  L9 w1.3: 89,119.5 J5.2@91.748,119.5 ; 91.748,116.752 J5.2@91.748,119.5 ; 91.748,122.248 J5.2@91.748,119.5 ; 91.8,114.8 J5.3@94.548,114.8 ; 94.496,119.5 J5.2@91.748,119.5 ; 94.548,112.052 J5.3@94.548,114.8 ; 94.548,117.548 J5.3@94.548,114.8 ; 97.296,114.8 J5.3@94.548,114.8
  BOTTOM_L10 w0.084: U23.2@41.723,91.766 41.723,90.616 v3(42.023,90.316) U23.49@43.523,88.816 ; v4(43.223,85.237) 43.323,85.337 U23.31@43.323,85.866
  BOTTOM_L10 w0.1: D85.1@27.959,153.017 D85.1@27.959,153.042 v3(27.959,153.366) ; 58.069,126.84 v4(58.069,127.272) ; U33_5.11@86.653,96.545 v3(87.103,96.545)
  BOTTOM_L10 w0.127: U12.74@14.15,16.81 v3(14.15,17.338) ; U12.71@15.65,16.81 v3(15.65,17.338) ; R481.1@45.374,107.942 v3(45.871,107.942) ; C64.2@67.125,13.791 v3(67.887,13.791) ; v3(72.604,8.187) C27.1@72.604,8.563 ; 74.7,37.3 75.191,37.3 75.263,37.372 75.827,37.372 76.7,38.244 76.7,38.8 ; v3(74.737,62.181) C71.1@74.737,62.529 ; v3(75.437,62.256) D12.1@75.437,62.604 ; v3(95.1,29.8) C246_6.1@95.5,29.8 ; v3(95.525,28.8) R473.1@95.525,29.2 ; v3(96.74,29.1) C179_6.1@96.74,29.5 ; R182.1@97.95,29.475 97.95,29.752 98.173,29.975 v3(98.2,29.975) 98.215,29.99 U27_6.2@98.215,30.585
